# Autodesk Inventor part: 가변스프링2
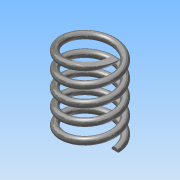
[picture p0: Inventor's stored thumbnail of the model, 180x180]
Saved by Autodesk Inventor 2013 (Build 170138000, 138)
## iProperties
Created: 2015-02
Part Number: 가변스프링2
Material: 강철, 탄소
Document SubType Name: Modeling
Designer: WINDOWS7
Density: 7.87 g/cm^3
Mass: 18.7439 g
Surface Area: 32.3998 cm^2
Volume: 2.3817 cm^3
Author: WINDOWS7
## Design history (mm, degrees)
sketch "스케치1"
  geometry: L1 (0, 0)-(11, 0); L2 (11, 0)-(11, 25.358); L3 (11, 25.358)-(0, 25.358); L4 (0, 25.358)-(0, 0); C1 r 1.5 at (11, 0)
  constraints: 8 end point, 2 parallel, 1 centre point, 1 coincident, 1 horizontal, 1 perpendicular
  dimensions: "d0" = 3 diameter of C1; "d2" = 22 diameter of L2 L4; "d3" = 25.35829 distance between parallel lines of L1 L3 (derived)
feature "코일1" sketch "스케치1" pitch "d4" = 10; turns "d6" = 5; dims "d5" = 25.35829 (= d3), "d7" = 0, angle "d8" = 90 deg, angle "d9" = 90 deg, "d10" = 0, "d11" = 0
feature "분할1"
node "작업 평면1"
feature "분할2"
node "솔리드1"
other parameters: "d12" = 90 deg
